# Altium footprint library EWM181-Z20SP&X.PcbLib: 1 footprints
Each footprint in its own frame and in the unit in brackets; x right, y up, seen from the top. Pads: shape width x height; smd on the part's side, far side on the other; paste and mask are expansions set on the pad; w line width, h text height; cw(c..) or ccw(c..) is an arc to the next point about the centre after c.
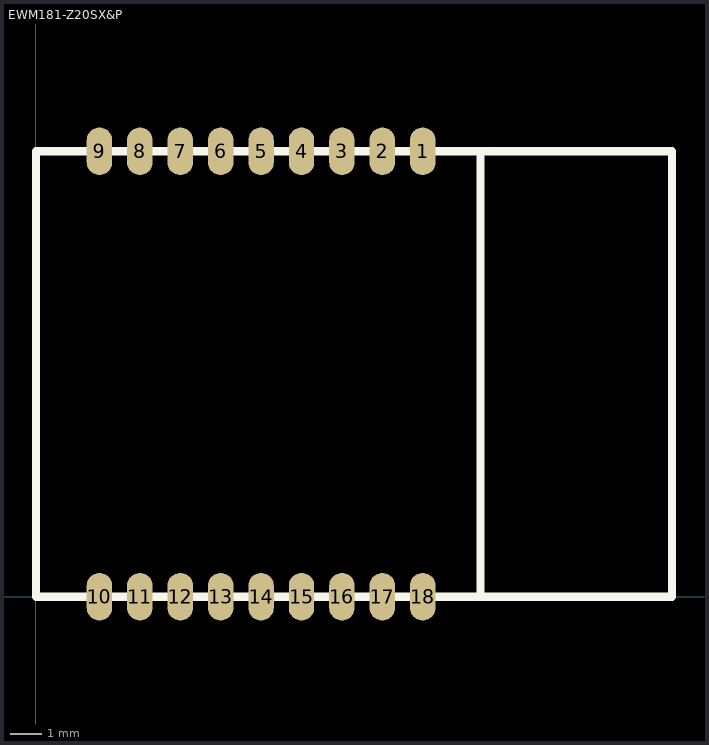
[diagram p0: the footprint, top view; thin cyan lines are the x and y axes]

## EWM181-Z20SX&P [mm]
pads (18):
  oval 0.8x1.5 smd: 1(12.16,14) 2(10.89,14) 3(9.62,14) 4(8.35,14) 5(7.08,14) 6(5.81,14) 7(4.54,14) 8(3.27,14) 9(2,14) 10(2,0) 11(3.27,0) 12(4.54,0) 13(5.81,0) 14(7.08,0) 15(8.35,0) 16(9.62,0) 17(10.89,0) 18(12.16,0)
Top Overlay:
  lines w0.254: 13.97,14 13.97,0 0,0 ; 0,0 0,14 20,14 20,0 0,0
